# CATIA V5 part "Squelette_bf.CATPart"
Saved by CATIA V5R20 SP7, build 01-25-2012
Part number: Squelette_bf
Publications: "Plan.2", "Droite.5", "Droite.6"
Bounding box of the stored display mesh (mm): x 0 to 20, y 4.214 to 12.243, z 122.499 to 192.752
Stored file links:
  G:\bon\Nouveau dossier\Squelette_bf.CATPart
  C:\Documents and Settings\cgirerd\Bureau\Copie de Copie de Nouveau dossier\765.CATProduct
  G:\bon\Nouveau dossier\mecanism.skl.CATProduct
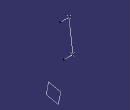
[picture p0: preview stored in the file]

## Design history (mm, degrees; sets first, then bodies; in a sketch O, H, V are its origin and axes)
Set1
  Point1 "B": linked copy from another document
  Point2 "F": linked copy from another document
  Plane1: linked copy from another document
Set2
  Line1: type PtPt, FirstPoint Point1, SecondPoint Point2
  Line2: type Normal, RefPoint Point1, RefSkin Plane1, Start 0, End 20
  Line3: type Normal, RefPoint Point2, RefSkin Plane1, Start 0, End 20
Body1 (main body)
